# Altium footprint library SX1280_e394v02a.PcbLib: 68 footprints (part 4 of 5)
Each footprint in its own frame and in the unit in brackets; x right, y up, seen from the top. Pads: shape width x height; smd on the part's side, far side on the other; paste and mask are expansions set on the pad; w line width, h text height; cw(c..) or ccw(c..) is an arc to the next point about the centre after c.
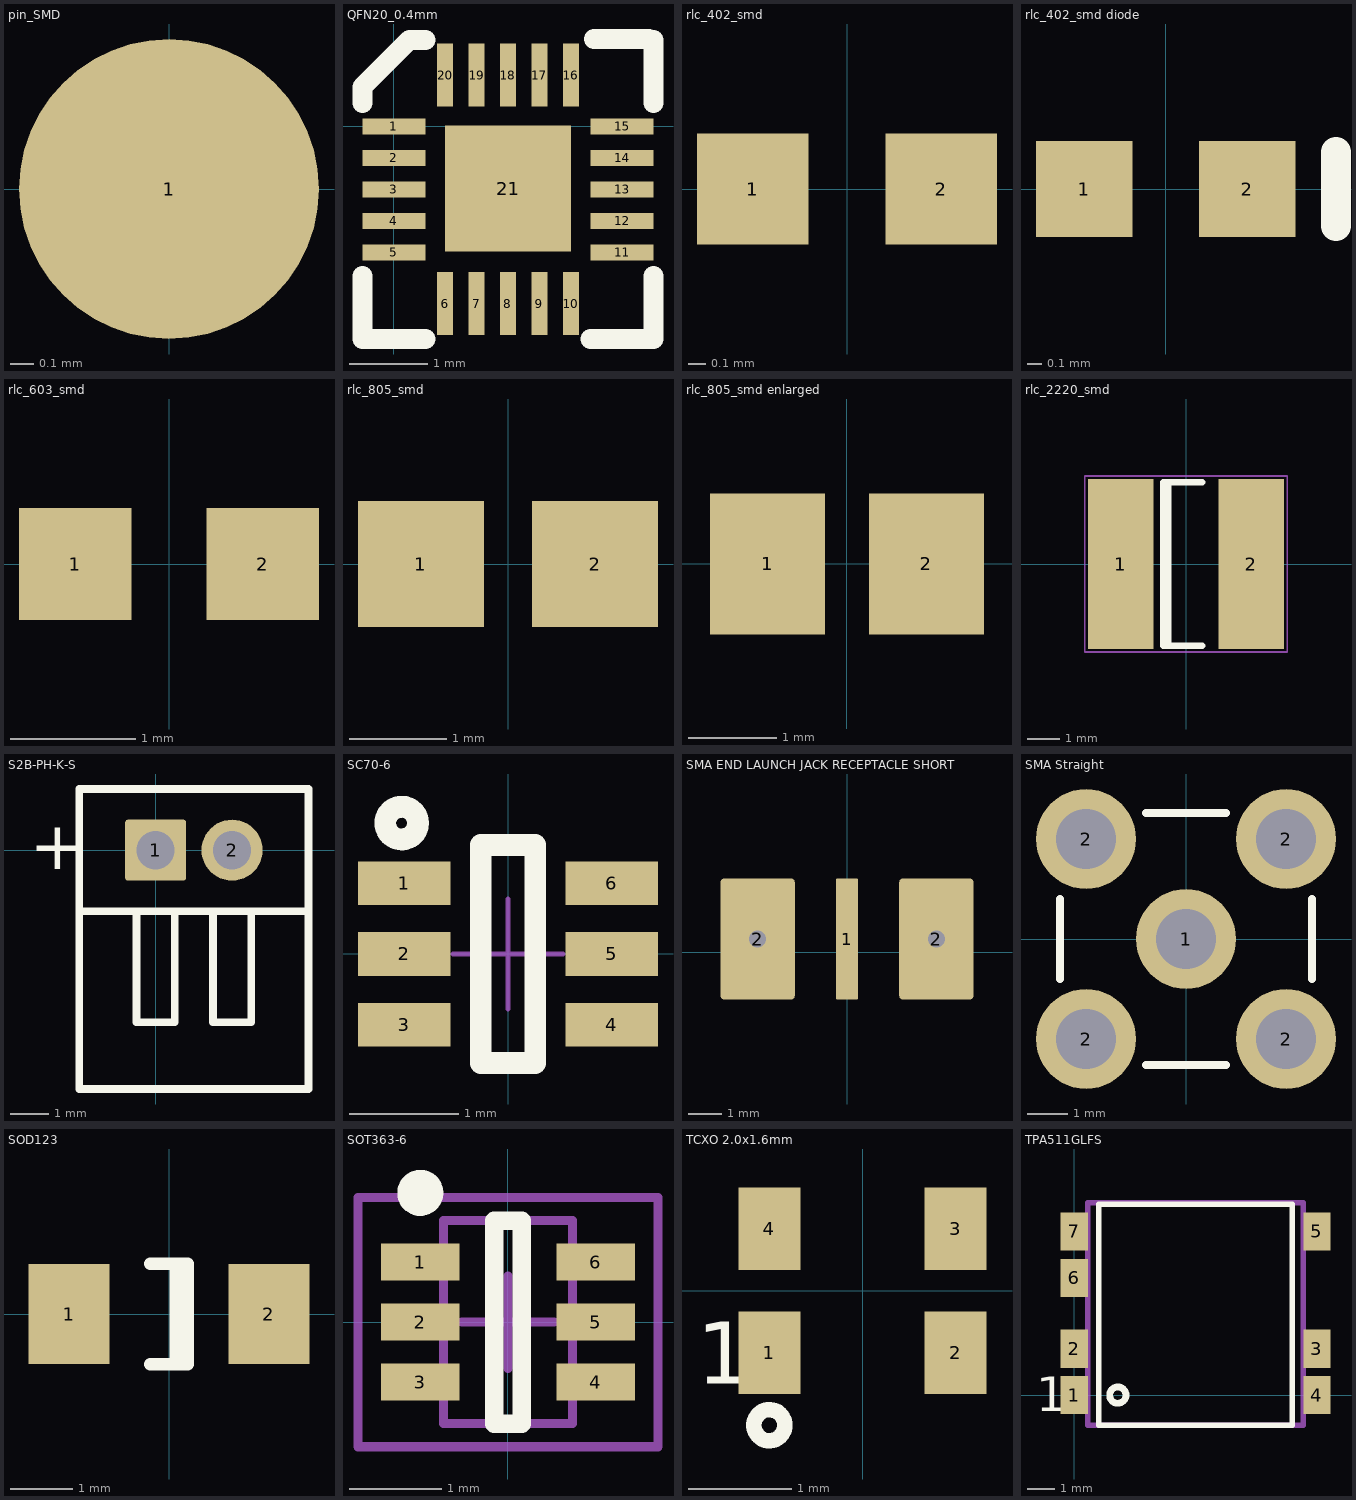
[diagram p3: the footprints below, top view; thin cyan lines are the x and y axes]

## pin_SMD [mm] "Generic Pin; 1 pin SMD"
height 0.5
pads (1):
  round 1.27 smd paste-1 mask+0.05: 1(0,0)

## QFN20_0.4mm [mm]
pads (21):
  rect 0.8x0.2 smd: 1(0,0) 2(0,-0.4) 3(0,-0.8) 4(0,-1.2) 5(0,-1.6) 11(2.9,-1.6) 12(2.9,-1.2) 13(2.9,-0.8) 14(2.9,-0.4) 15(2.9,0)
  rect 0.2x0.8 smd: 6(0.65,-2.25) 7(1.05,-2.25) 8(1.45,-2.25) 9(1.85,-2.25) 10(2.25,-2.25) 16(2.25,0.65) 17(1.85,0.65) 18(1.45,0.65) 19(1.05,0.65) 20(0.65,0.65)
  rect 1.6x1.6 smd: 21(1.45,-0.79)
Top Overlay:
  lines w0.254: -0.4,-1.9 -0.4,-2.7 0.4,-2.7 ; -0.4,0.3 -0.4,0.5 0.2,1.1 0.4,1.1 ; 2.5,-2.7 3.3,-2.7 3.3,-1.9 ; 2.54,1.11 3.24,1.11 ; 3.3,0.3 3.3,1.1

## rlc_402_smd [mm] "Chip SMD component 402; Body 1.0 x 0.5 mm (LxW typ)"
height 0.8
pads (2):
  rect 0.65x0.65 smd mask+0.05: 1(-0.55,0) 2(0.55,0)
3D body: height 0.8, standoff 0.2, extent -0.875,-0.325 0.875,0.325

## rlc_402_smd diode [mm] "Chip SMD component 402; Body 1.0 x 0.5 mm (LxW typ)"
height 0.8
pads (2):
  rect 0.65x0.65 smd mask+0.05: 1(-0.55,0) 2(0.55,0)
Top Overlay:
  lines w0.2: 1.15,-0.25 1.15,0.25

## rlc_603_smd [mm] "Chip SMD component 603; Body 1.6 x 0.8mm (LxW typ)"
height 1
pads (2):
  rect 0.9x0.9 smd paste+0 mask+0.05: 1(-0.75,0) 2(0.75,0)

## rlc_805_smd [mm] "Chip SMD component 805; Body 2.0 x 1.25 mm (LxW typ)"
height 1.4
pads (2):
  rect 1.3x1.3 smd mask+0.05: 1(-0.9,0) 2(0.9,0)

## rlc_805_smd enlarged [mm] "Chip SMD component 805; Body 2.0 x 1.25 mm (LxW typ)"
height 1.4
pads (2):
  rect 1.3x1.6 smd mask+0.05: 1(-0.9,0) 2(0.9,0)

## rlc_2220_smd [mm] "Chip SMD component ; Body 5.7 x 5.0 mm (LxW typ)"
height 5
pads (2):
  rect 2x5.2 smd mask+0.05: 1(-2,0) 2(2,0)
Top Overlay:
  lines w0.2: -0.55,-2.5 -0.55,2.5 ; 0.5,-2.5 -0.7,-2.5 -0.7,2.5 0.5,2.5
Mechanical 15:
  lines w0.05: -3.1,-2.7 -3.1,2.7 3.1,2.7 3.1,-2.7 -3.1,-2.7

## S2B-PH-K-S [mm] "S2B-PH-K-S; JST; Battery Connector side entry; Header; 2 Position"
pads (2):
  rrect10% 1.6x1.6 hole 1: 1(0,0)
  round 1.6 hole 1: 2(2,0)
Top Overlay:
  lines w0.2: -2,-1.6 4,-1.6 ; -0.5,-1.6 -0.5,-4.5 0.5,-4.5 0.5,-1.6 ; 1.5,-1.6 1.5,-4.5 2.5,-4.5 2.5,-1.6 ; -2,-6.25 4,-6.25 4,1.6 -2,1.6 -2,-6.25
  text "+" at -3.3,-0.5 h1.27
3D body: height 2.95, standoff 0, extent -2,-6.25 4,1.6

## SC70-6 [mm] "SC70 6-Leads, Body 2.0x1.25mm, Pitch 0.65mm"
height 1.45
pads (6):
  rect 0.85x0.4 smd mask+0.05: 1(-0.95,0.65) 2(-0.95,0) 3(-0.95,-0.65) 4(0.95,-0.65) 5(0.95,0) 6(0.95,0.65)
Top Overlay:
  circle w0.2: c-0.975,1.2 r0.15
  lines w0.2: -0.25,-1 0.25,-1 0.25,1 -0.25,1 -0.25,-1
Mechanical 15:
  lines w0.05: -0.5,0 0.5,0 ; 0,-0.5 0,0.5
3D body: height 1.45, standoff 0, extent -0.625,-1 0.625,1

## SMA END LAUNCH JACK RECEPTACLE SHORT [mm] "SMA Connector - End Launch Jack Receptacle - Short"
height 8
pads (3):
  rrect10% 0.65x3.6 smd paste+0 mask+0.05: 1(0,0.4)
  rrect10% 2.2x3.6 hole 0.5 mask+0.1: 2(-2.65,0.4) 2(2.65,0.4)
3D body: height 2.95, standoff 0, extent -0.325,-0.4 0.325,0.4

## SMA Straight [mm] "SMA Connector; Straight"
height 10
pads (5):
  round 2.5 hole 1.5 paste+0 mask+0.1: 1(0,0) 2(-2.5,-2.5) 2(-2.5,2.5) 2(2.5,-2.5) 2(2.5,2.5)
Top Overlay:
  lines w0.2: -3.15,-1 -3.15,1 ; -1,-3.15 1,-3.15 ; -1,3.15 1,3.15 ; 3.15,-1 3.15,1
Mechanical 1:
  circle w0.025: c0,0 r0.2

## SOD123 [mm] "SOD123; Chip Diode; Body  2.7 x 1.6 mm (LxW typ)"
height 1.35
pads (2):
  rect 1.3x1.6 smd mask+0.05: 1(-1.6,0) 2(1.6,0)
Top Overlay:
  lines w0.2: -0.3,-0.8 0.3,-0.8 0.3,0.8 -0.3,0.8 ; 0.11,-0.8 0.11,0.8

## SOT363-6 [mm] "SOT363, 6-Leads, Body 2x1.3mm, Pitch 0.65mm, Lead Span 2.1mm, IPC Medium Density"
height 1
pads (6):
  rect 0.85x0.4 smd mask+0.05: 1(-0.95,0.65) 2(-0.95,0) 3(-0.95,-0.65) 4(0.95,-0.65) 5(0.95,0) 6(0.95,0.65)
Top Overlay:
  circle w0.25: c-0.95,1.4 r0.125
  lines w0.2: -0.15,-1.1 0.15,-1.1 0.15,1.1 -0.15,1.1 -0.15,-1.1
Mechanical 13:
  lines w0.1: -0.7,-1.1 -0.7,1.1 0.7,1.1 0.7,-1.1 -0.7,-1.1
Mechanical 15:
  lines w0.1: -0.5,0 0.5,0 ; 0,-0.5 0,0.5 ; -1.625,-1.35 -1.625,1.35 1.625,1.35 1.625,-1.35 -1.625,-1.35
3D body: height 1, standoff 0, extent -0.7,-1.1 0.7,1.1

## TCXO 2.0x1.6mm [mm] "SMD 2.0x1.6mm for TCXO or VCTCXO"
height 1
pads (4):
  rect 0.6x0.8 smd mask+0.05: 1(-0.9,-0.6) 2(0.9,-0.6) 3(0.9,0.6) 4(-0.9,0.6)
Top Overlay:
  circle w0.15: c-0.9,-1.3 r0.15
  text "1" at -1.6,-0.9 h0.6
3D body: height 1, standoff 0, extent -1,-0.8 1,0.8

## TPA511GLFS [mm] "Joystick; TPA511GLFS; TPA Series; C&K Components"
height 1.45
pads (7):
  rect 1x1.4 smd mask+0.05: 1(0,0) 2(0,1.7) 3(8.9,1.7) 4(8.9,0) 5(8.9,6) 6(0,4.3) 7(0,6)
Top Overlay:
  circle w0.25: c1.6,0 r0.3
  lines w0.2: 0.9,-1.1 0.9,7 8,7 8,-1.1 0.9,-1.1
  text "1" at -1.4,-0.6 h1.27
Mechanical 15:
  lines w0.2: 0.5,-1.1 0.5,7.05 8.4,7.05 8.4,-1.1 0.5,-1.1
3D body: height 2.95, standoff 0, extent 0.4,-1.1 8.5,7.05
